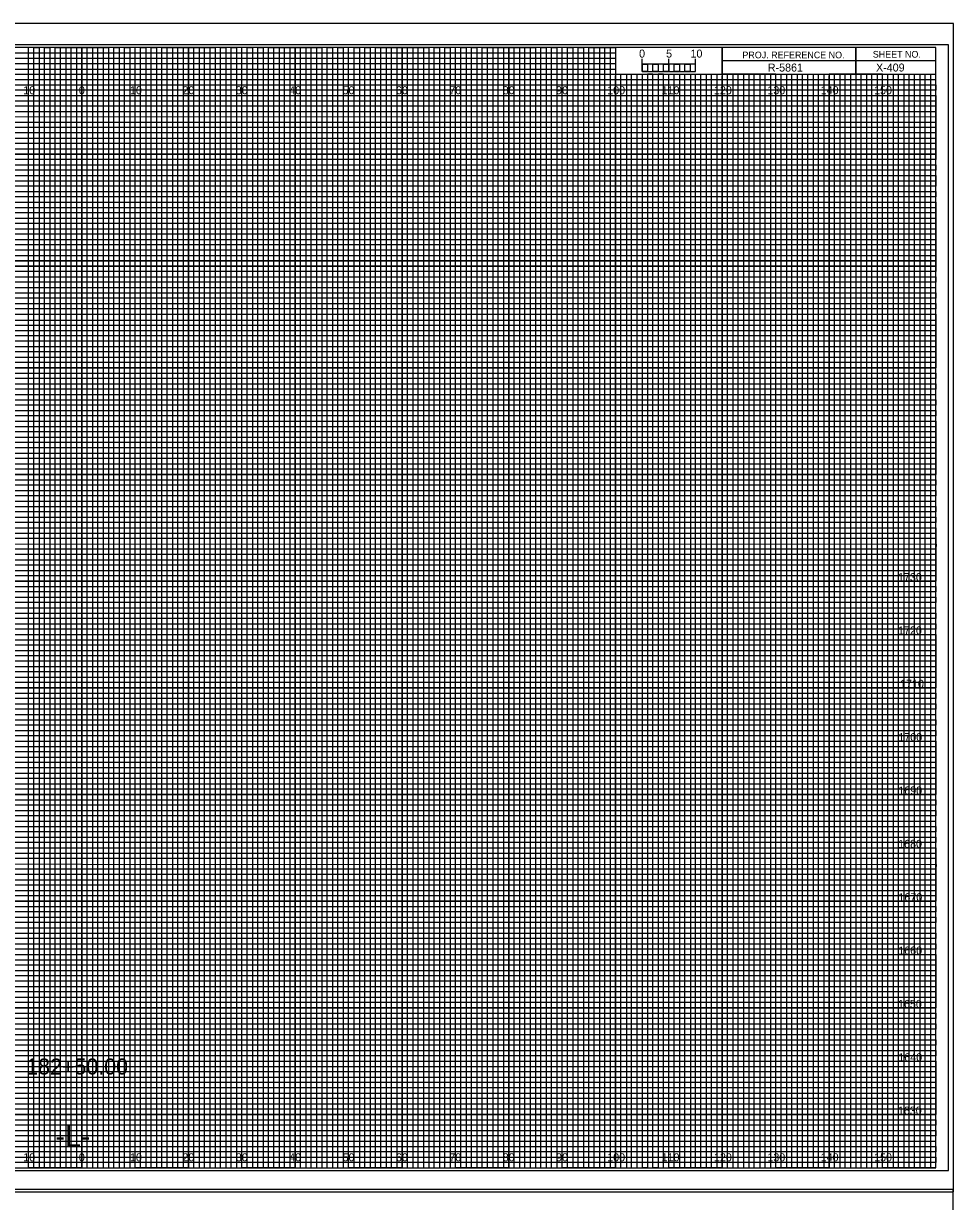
# Model space of a CAD drawing. Extents: x -13 to 323, y -5 to 6154.
# Drawn here: x 149.1 to 323.3, y 1093.7 to 1314.5 of the extents above; entities that cross this region are included whole.
import ezdxf

# ---------------------------------------------------------------- set-up
doc = ezdxf.new("R2010")
doc.units = 0
for name, color, linetype in [('Exist CMT Ground Line', 7, 'Continuous'), ('Prop Horizontal Alignment', 7, 'Continuous'), ('Prop Retaining Wall', 7, 'Continuous'), ('Prop XS Alignment Label', 7, 'Continuous'), ('Prop XS Bar Scale Labels', 7, 'Continuous'), ('Prop XS DDE', 7, 'Continuous'), ('Prop XS DDE Elevations', 7, 'Continuous'), ('Prop XS DDE Slope Text', 7, 'Continuous'), ('Prop XS Earthwork Shape', 7, 'Continuous'), ('Prop XS Elevation Labels', 7, 'Continuous'), ('Prop XS Project Number', 7, 'Continuous'), ('Prop XS Sheet Number', 7, 'Continuous'), ('Prop XS Station Labels', 7, 'Continuous'), ('Raster_Level_0', 7, 'Continuous'), ('Scratch_Level_3', 7, 'Continuous'), ('Sheet Cutting Line CELL', 7, 'Continuous')]:
    doc.layers.add(name, color=color, linetype=linetype)

msp = doc.modelspace()

# ---------------------------------------------------------------- linework, layer by layer
at = {"layer": 'Exist CMT Ground Line'}
for p, q in [((265, 1305.49), (265, 1307.9)), ((265, 1306.9), (265, 1307.9)), ((270, 1305.49), (270, 1307.9)), ((275, 1305.49), (275, 1307.9)), ((275, 1306.9), (275, 1307.9))]:
    msp.add_line(p, q, dxfattribs=at)
for points in [[(275, 1306.9), (265, 1306.9), (265, 1305.49), (275, 1305.49)], [(265, 1306.9), (266, 1306.9), (266, 1305.49), (265, 1305.49)], [(267, 1306.9), (268, 1306.9), (268, 1305.49), (267, 1305.49)], [(269, 1306.9), (270, 1306.9), (270, 1305.49), (269, 1305.49)], [(271, 1306.9), (272, 1306.9), (272, 1305.49), (271, 1305.49)], [(273, 1306.9), (274, 1306.9), (274, 1305.49), (273, 1305.49)]]:
    msp.add_lwpolyline(points, close=True, dxfattribs=at)
at = {"layer": 'Prop Retaining Wall'}
for p, q in [((0, 1309), (260, 1309)), ((260, 1307.98), (0, 1307.98)), ((0, 1307), (260, 1307)), ((260, 1309), (260, 1307.98)), ((260, 1307), (260, 1305.89)), ((260, 1305.89), (0, 1305.89)), ((0, 1304), (320, 1304))]:
    msp.add_line(p, q, dxfattribs=at)
for points in [[(0, 1303), (270, 1303), (320, 1303), (320, 1302), (0, 1302)], [(0, 1301), (320, 1301), (320, 1299), (0, 1299)], [(0, 1298), (320, 1298), (320, 1297), (0, 1296.98)], [(0, 1296), (320, 1296), (320, 1294), (0, 1294)], [(0, 1293), (320, 1293), (320, 1292), (0, 1292)], [(0, 1291), (320, 1291), (320, 1289), (0, 1289)], [(0, 1288), (320, 1288), (320, 1287), (0, 1287)], [(0, 1286), (320, 1286), (320, 1284), (0, 1284)], [(0, 1283), (320, 1283), (320, 1282), (0, 1282)], [(0, 1281), (320, 1281), (320, 1279), (0, 1279)], [(0, 1278), (320, 1278), (320, 1277), (0, 1277)], [(0, 1276), (320, 1276), (320, 1273.95), (320, 1273), (320, 1272), (0, 1272)], [(0, 1274), (320, 1274), (320, 1273), (0, 1273)], [(0, 1271), (320, 1271), (320, 1269), (0, 1269.03)], [(0, 1269.03), (320, 1269), (320, 1268), (0, 1268)], [(0, 1267), (320, 1267), (320, 1266), (0, 1266)], [(0, 1264), (320, 1264), (320, 1263), (0, 1263)], [(0, 1262), (320, 1262), (320, 1261), (0, 1261)], [(-0.07, 1258.89), (320, 1258.89), (320, 1257.88), (-0.07, 1257.88)], [(0, 1257), (320, 1257), (320, 1256), (0, 1256)], [(0, 1254), (320, 1254), (320, 1253), (0, 1253)], [(0, 1252), (320, 1252), (320, 1251), (0, 1251)], [(0, 1249), (320, 1249), (320, 1248), (0, 1248)], [(0, 1247), (320, 1247), (320, 1246), (0, 1246)], [(0, 1244), (320, 1244), (320, 1243), (0, 1243)], [(0, 1242), (320, 1242), (320, 1241), (0, 1241)], [(0, 1239), (320, 1239), (319.99, 1237.98), (0, 1238)], [(0, 1237), (320, 1237), (320, 1236), (0, 1236)], [(0, 1234), (320, 1234), (320, 1233), (0, 1233)], [(0, 1232), (320, 1232), (320, 1231), (0, 1231)], [(0, 1229), (320, 1229), (320, 1228), (0, 1228)], [(0, 1227), (320, 1227), (320, 1226), (0, 1226)], [(0, 1224), (320, 1224), (320, 1223), (0, 1223)], [(0, 1222), (320, 1222), (320, 1221), (0, 1221)], [(0, 1219), (320, 1219), (320, 1218), (0, 1218)], [(0, 1216.99), (320.07, 1216.91), (320, 1216), (0, 1216)], [(0, 1214), (320, 1214), (320, 1213), (0, 1213)], [(0, 1212), (320, 1212), (320, 1211), (0, 1211)], [(0, 1209), (320, 1209), (320, 1208), (0, 1208)], [(0, 1207), (320, 1207), (320, 1206), (0, 1206)], [(0, 1204), (320, 1204), (320, 1203), (0, 1203)], [(0, 1202), (320, 1202), (320, 1201), (0, 1201)], [(0, 1199), (320, 1199), (320, 1198), (0, 1198)], [(0, 1197), (320, 1197), (320, 1196), (0, 1196)], [(0, 1194), (320, 1194), (320, 1193), (0, 1193)], [(0, 1192), (320, 1192), (320, 1191), (0, 1191)], [(0, 1189), (320, 1189), (320, 1188), (0, 1188)], [(0, 1187), (320, 1187), (320, 1186), (0, 1186)], [(0, 1184), (320, 1184), (320, 1183), (0, 1183)], [(0, 1182), (320, 1182), (320, 1181), (0, 1181)], [(0, 1179), (320, 1179), (319.99, 1177.98), (0, 1178)], [(0, 1177), (320, 1177), (320, 1176), (0, 1176)], [(0, 1174), (320, 1174), (320, 1173), (0, 1173)], [(0, 1172), (320, 1172), (320, 1171), (0, 1171)], [(0, 1169), (320, 1169), (320, 1168), (0, 1168)], [(0, 1167), (320, 1167), (320, 1166), (0, 1166)], [(0, 1164), (320, 1164), (320, 1163), (0, 1163)], [(0, 1162), (320, 1162), (320, 1161), (0, 1161)], [(0, 1159), (320, 1159), (320, 1158), (0, 1158)], [(0, 1156.99), (320.07, 1156.91), (320, 1156), (0, 1156)], [(0, 1154), (320, 1154), (320, 1153), (0, 1153)], [(0, 1152), (320, 1152), (320, 1151), (0, 1151)], [(0, 1149), (320, 1149), (320, 1148), (0, 1148)], [(0, 1147), (320, 1147), (320, 1146), (0, 1146)], [(0, 1144), (320, 1144), (320, 1143), (0, 1143)], [(0, 1142), (320, 1142), (320, 1141), (0, 1141)], [(0, 1139), (320, 1139), (320, 1138), (0, 1138)], [(0, 1137), (320, 1137), (320, 1136), (0, 1136)], [(0, 1134), (320, 1134), (320, 1133), (0, 1133)], [(0, 1132), (320, 1132), (320, 1131), (0, 1131)], [(0, 1129), (320, 1129), (320, 1128), (0, 1128)], [(0, 1127), (320, 1127), (320, 1126), (0, 1126)], [(0, 1124), (320, 1124), (320, 1123), (0, 1123)], [(0, 1122), (320, 1122), (320, 1121), (0, 1121)], [(0, 1119), (320, 1119), (320, 1118), (0, 1118)], [(0, 1117), (320, 1117), (320, 1116), (0, 1116)], [(0, 1114), (320, 1114), (320, 1113), (0, 1113)], [(0, 1112), (320, 1112), (320, 1111), (0, 1111)], [(0, 1109), (320, 1109), (320, 1108), (0, 1108)], [(0, 1107), (320, 1107), (320, 1106), (0, 1106)], [(0, 1104), (320, 1104), (320, 1103), (0, 1103)], [(0, 1102), (320, 1102), (320, 1101), (0, 1101)]]:
    msp.add_lwpolyline(points, dxfattribs=at)
at = {"layer": 'Prop XS Alignment Label'}
for p, q in [((305, 1310), (305, 1305)), ((305, 1305), (305, 1310)), ((280, 1307.5), (280, 1305)), ((320, 1307.49), (280, 1307.49)), ((280, 1305), (320, 1305))]:
    msp.add_line(p, q, dxfattribs=at)
for points in [[(320, 1310), (0, 1310), (0, 1100), (320, 1100)], [(280, 1310), (260, 1310), (260, 1305.03), (280, 1305.03)], [(320, 1310), (280, 1310), (280, 1305), (320, 1305)]]:
    msp.add_lwpolyline(points, close=True, dxfattribs=at)
at = {"layer": 'Prop XS DDE'}
for points in [[(-13.4, 1095.5), (323.3, 1095.5), (323.3, 1314.5), (-13.4, 1314.5)], [(-13.44, 876.95), (323.26, 876.95), (323.26, 1095.95), (-13.44, 1095.95)]]:
    msp.add_lwpolyline(points, close=True, dxfattribs=at)
at = {"layer": 'Prop XS DDE Elevations'}
for p, q in [((150, 1100), (150, 1310)), ((160, 1100), (160, 1310)), ((170, 1100), (170, 1310)), ((180, 1100), (180, 1310)), ((190, 1100), (190, 1310)), ((200, 1100), (200, 1310)), ((210, 1100), (210, 1310)), ((220, 1100), (220, 1310)), ((230, 1100), (230, 1310)), ((240, 1100), (240, 1310)), ((250, 1100), (250, 1310)), ((260, 1100), (260, 1304.69)), ((270, 1100), (270, 1304.69)), ((280, 1100), (280, 1304.69)), ((290, 1100), (290, 1304.69)), ((300, 1100), (300, 1304.69)), ((310, 1100), (310, 1304.69)), ((0, 1300), (320, 1300)), ((0, 1290), (320, 1290)), ((0, 1280), (320, 1280)), ((0, 1270), (320, 1270)), ((0, 1260), (320, 1260)), ((0, 1250), (320, 1250)), ((0, 1240), (320, 1240)), ((0, 1230), (320, 1230)), ((0, 1220), (320, 1220)), ((0, 1210), (320, 1210)), ((0, 1200), (320, 1200)), ((0, 1190), (320, 1190)), ((0, 1180), (320, 1180)), ((0, 1170), (320, 1170)), ((0, 1160), (320, 1160)), ((0, 1150), (320, 1150)), ((0, 1140), (320, 1140)), ((0, 1130), (320, 1130)), ((0, 1120), (320, 1120)), ((0, 1110), (320, 1110))]:
    msp.add_line(p, q, dxfattribs=at)
at = {"layer": 'Prop XS DDE Slope Text'}
msp.add_lwpolyline([(-10.8, 1099.5), (322.4, 1099.5), (322.4, 1310.5), (-10.8, 1310.5)], close=True, dxfattribs=at)
at = {"layer": 'Prop XS Earthwork Shape'}
for p, q in [((150, 1310), (140, 1310)), ((150, 1100), (150, 1310)), ((170, 1310), (160, 1310)), ((160, 1310), (160, 1100)), ((170, 1100), (170, 1310)), ((190, 1310), (180, 1310)), ((180, 1310), (180, 1100)), ((190, 1100), (190, 1310)), ((210, 1310), (200, 1310)), ((200, 1310), (200, 1100)), ((210, 1100), (210, 1310)), ((230, 1310), (220, 1310)), ((220, 1310), (220, 1100)), ((230, 1100), (230, 1310)), ((250, 1310), (240, 1310)), ((240, 1310), (240, 1100)), ((250, 1100), (250, 1310)), ((260, 1310), (260, 1100)), ((270, 1100), (270, 1305)), ((290, 1305), (280, 1305)), ((280, 1305), (280, 1100)), ((290, 1100), (290, 1305)), ((310, 1305), (300, 1305)), ((300, 1305), (300, 1100)), ((310, 1100), (310, 1305)), ((160, 1100), (150, 1100)), ((180, 1100), (170, 1100)), ((200, 1100), (190, 1100)), ((220, 1100), (210, 1100)), ((240, 1100), (230, 1100)), ((260, 1100), (250, 1100)), ((280, 1100), (270, 1100)), ((300, 1100), (290, 1100)), ((320, 1100), (310, 1100)), ((320, 1100), (320, 1100))]:
    msp.add_line(p, q, dxfattribs=at)
for points in [[(0, 1300), (320, 1300), (320, 1290), (0, 1290)], [(0, 1280), (320, 1280), (320, 1270), (0, 1270)], [(0, 1260), (320, 1260), (320, 1250), (0, 1250)], [(0, 1240), (320, 1240), (320, 1230), (0, 1230)], [(0, 1220), (320, 1220), (320, 1210), (0, 1210)], [(0, 1200), (320, 1200), (320, 1190), (0, 1190)], [(0, 1180), (320, 1180), (320, 1170), (0, 1170)], [(0, 1160), (320, 1160), (320, 1150), (0, 1150)], [(0, 1140), (320, 1140), (320, 1130), (0, 1130)], [(0, 1120), (320, 1120), (320, 1110), (0, 1110)]]:
    msp.add_lwpolyline(points, dxfattribs=at)
at = {"layer": 'Prop XS Elevation Labels'}
for p, q in [((267, 1305), (266.01, 1305)), ((266.01, 1305), (266.01, 1100)), ((267, 1100), (267, 1305)), ((269, 1305), (268, 1305)), ((268, 1305), (268, 1100)), ((269, 1100), (269, 1305)), ((266.01, 1100), (265, 1100)), ((268, 1100), (267, 1100))]:
    msp.add_line(p, q, dxfattribs=at)
for points in [[(150, 1100), (151, 1100), (151, 1310), (152, 1310), (152, 1100)], [(152, 1100), (153, 1100), (153, 1310), (154, 1310), (154, 1100)], [(155, 1100), (156, 1100), (156, 1310), (157, 1310), (157, 1100)], [(157, 1100), (158, 1100), (158, 1310), (159, 1310), (159, 1100)], [(160, 1100), (161, 1100), (161, 1310), (162, 1310), (162, 1100)], [(162, 1100), (163, 1100), (163, 1310), (164, 1310), (164, 1100)], [(165, 1100), (166, 1100), (166, 1310), (167, 1310), (167, 1100)], [(167, 1100), (168, 1100), (168, 1310), (169, 1310), (169, 1100)], [(170, 1100), (171, 1100), (171, 1310), (172, 1310), (172, 1100)], [(172, 1100), (173, 1100), (173, 1310), (174, 1310), (174, 1100)], [(175, 1100), (176, 1100), (176, 1310), (177, 1310), (177, 1100)], [(177, 1100), (178, 1100), (178, 1310), (179, 1310), (179, 1100)], [(180, 1100), (181, 1100), (181, 1310), (182, 1310), (182, 1100)], [(182, 1100), (183, 1100), (183, 1310), (184, 1310), (184, 1100)], [(185, 1100), (186, 1100), (186, 1310), (187, 1310), (187, 1100)], [(187, 1100), (188, 1100), (188, 1310), (189, 1310), (189, 1100)], [(190, 1100), (191, 1100), (191, 1310), (192, 1310), (192, 1100)], [(192, 1100), (193, 1100), (193, 1310), (194, 1310), (194, 1100)], [(195, 1100), (196, 1100), (196, 1310), (197, 1310), (197, 1100)], [(197, 1100), (198, 1100), (198, 1310), (199, 1310), (199, 1100)], [(200, 1100), (201, 1100), (201, 1310), (202, 1310), (202, 1100)], [(202, 1100), (203, 1100), (203, 1310), (204, 1310), (204, 1100)], [(205, 1100), (206, 1100), (206, 1310), (207, 1310), (207, 1100)], [(207, 1100), (208, 1100), (208, 1310), (209, 1310), (209, 1100)], [(210, 1100), (211, 1100), (211, 1310), (212, 1310), (212, 1100)], [(212, 1100), (213, 1100), (213, 1310), (214, 1310), (214, 1100)], [(215, 1100), (216, 1100), (216, 1310), (217, 1310), (217, 1100)], [(217, 1100), (218, 1100), (218, 1310), (219, 1310), (219, 1100)], [(220, 1100), (221, 1100), (221, 1310), (222, 1310), (222, 1100)], [(222, 1100), (223, 1100), (223, 1310), (224, 1310), (224, 1100)], [(225, 1100), (226, 1100), (226, 1310), (227, 1310), (227, 1100)], [(227, 1100), (228, 1100), (228, 1310), (229, 1310), (229, 1100)], [(230, 1100), (231, 1100), (231, 1310), (232, 1310), (232, 1100)], [(232, 1100), (233, 1100), (233, 1310), (234, 1310), (234, 1100)], [(235, 1100), (236, 1100), (236, 1310), (237, 1310), (237, 1100)], [(237, 1100), (238, 1100), (238, 1310), (239, 1310), (239, 1100)], [(240, 1100), (241, 1100), (241, 1310), (242, 1310), (242, 1100)], [(242, 1100), (243, 1100), (243, 1310), (244, 1310), (244, 1100)], [(245, 1100), (246, 1100), (246, 1310), (247, 1310), (247, 1100)], [(247, 1100), (248, 1100), (248, 1310), (249, 1310), (249, 1100)], [(250, 1100), (251, 1100), (251, 1310), (252, 1310), (252, 1100)], [(252, 1100), (253, 1100), (253, 1310), (254, 1310), (254, 1100)], [(255, 1100), (256, 1100), (256, 1310), (257, 1310), (257, 1100)], [(257, 1100), (258, 1100), (258, 1310), (259, 1310), (259, 1100)], [(260, 1100), (261, 1100), (261, 1305), (262.02, 1305), (262.02, 1100)], [(262, 1100), (263, 1100), (263, 1305), (263.99, 1305), (263.99, 1100)], [(270, 1100), (270.98, 1100), (270.98, 1305), (272, 1305), (272, 1100)], [(272, 1100), (273, 1100), (273, 1305), (274.05, 1305), (274.05, 1100)], [(275, 1100), (276, 1100), (276, 1305), (277, 1305), (277, 1100)], [(277, 1100), (278, 1100), (278, 1305), (279, 1305), (279, 1100)], [(280, 1100), (281, 1100), (281, 1305), (282, 1305), (282, 1100)], [(282, 1100), (283, 1100), (283, 1305), (284, 1305), (284, 1100)], [(285, 1100), (286, 1100), (286, 1305), (287, 1305), (287, 1100)], [(287, 1100), (288, 1100), (288, 1305), (289, 1305), (289, 1100)], [(290, 1100), (291, 1100), (291, 1305), (292, 1305), (292, 1100)], [(292, 1100), (293, 1100), (293, 1305), (294, 1305), (294, 1100)], [(295, 1100), (296, 1100), (296, 1305), (297, 1305), (297, 1100)], [(297, 1100), (298, 1100), (298, 1305), (299, 1305), (299, 1100)], [(300, 1100), (301, 1100), (301, 1305), (302, 1305), (302, 1100)], [(302, 1100), (303, 1100), (303, 1305), (304, 1305), (304, 1100)], [(305, 1100), (306, 1100), (306, 1305), (307, 1305), (307, 1100)], [(307, 1100), (308, 1100), (308, 1305), (309, 1305), (309, 1100)], [(310, 1100), (311, 1100), (311, 1305), (312, 1305), (312, 1100)], [(312, 1100), (313, 1100), (313, 1305), (314, 1305), (314, 1100)], [(315, 1100), (316, 1100), (316, 1305), (317, 1305), (317, 1100)], [(317, 1100), (318, 1100), (318, 1305), (319, 1305), (319, 1100)]]:
    msp.add_lwpolyline(points, dxfattribs=at)
at = {"layer": 'Prop XS Station Labels'}
for points in [[(145, 1100), (155, 1100), (155, 1310), (165, 1310), (165, 1100), (175, 1100), (175, 1310), (185, 1310), (185, 1100), (195, 1100), (195, 1310), (205, 1310), (205, 1100), (215, 1100), (215, 1310), (225, 1310), (225, 1100), (235, 1100), (235, 1310), (245, 1310), (245, 1100), (255, 1100), (255, 1310), (259.93, 1310), (260, 1310), (260, 1305), (264.99, 1305), (264.99, 1100), (275, 1100), (275, 1305), (285, 1305), (285, 1100), (295, 1100), (295, 1305), (305, 1305), (305, 1100), (315, 1100), (315, 1305)], [(0, 1305), (275, 1305)], [(0, 1285), (320, 1285), (320, 1295), (0, 1295)], [(0, 1265), (320, 1265), (320, 1275), (0, 1275)], [(0, 1245), (320, 1245), (320, 1255), (0, 1255)], [(0, 1225), (320, 1225), (320, 1235), (0, 1235)], [(0, 1205), (320, 1205), (320, 1215), (0, 1215)], [(0, 1185), (320, 1185), (320, 1195), (0, 1195)], [(0, 1165), (320, 1165), (320, 1175), (0, 1175)], [(0, 1145), (320, 1145), (320, 1155), (0, 1155)], [(0, 1125), (320, 1125), (320, 1135), (0, 1135)], [(0, 1105), (320, 1105), (320, 1115), (0, 1115)]]:
    msp.add_lwpolyline(points, dxfattribs=at)
at = {"layer": 'Sheet Cutting Line CELL'}
for p, q in [((323.3, 1314.5), (-13.4, 1314.5)), ((323.26, 1095.95), (-13.44, 1095.95)), ((-13.4, 1095.5), (323.3, 1095.5))]:
    msp.add_line(p, q, dxfattribs=at)

# ---------------------------------------------------------------- texts
at = {"layer": 'Exist CMT Ground Line'}
msp.add_text('0', height=1.5, dxfattribs=at).set_placement((264.41, 1308.12))
at = {"layer": 'Prop Horizontal Alignment'}
msp.add_text('182+50.00', height=3, dxfattribs=at).set_placement((149.59, 1117.52))
at = {"layer": 'Prop XS Alignment Label'}
for s, height, p in [('PROJ. REFERENCE NO.', 1.25, (283.77, 1307.99)), ('SHEET NO.', 1.25, (308.19, 1308.12)), ('-L-', 4, (155.06, 1104))]:
    msp.add_text(s, height=height, dxfattribs=at).set_placement(p)
at = {"layer": 'Prop XS Bar Scale Labels'}
for s, p in [('5', (269.47, 1308.12)), ('10', (274.04, 1308.12))]:
    msp.add_text(s, height=1.5, dxfattribs=at).set_placement(p)
at = {"layer": 'Prop XS Project Number'}
msp.add_text('R-5861', height=1.5, dxfattribs=at).set_placement((288.53, 1305.5))
at = {"layer": 'Prop XS Sheet Number'}
msp.add_text('X-409', height=1.5, dxfattribs=at).set_placement((308.8, 1305.51))
at = {"layer": 'Raster_Level_0'}
for s, p in [('10', (149.04, 1301.25)), ('0', (159.45, 1301.25)), ('0', (159.45, 1301.25)), ('10', (169.04, 1301.25)), ('20', (178.86, 1301.25)), ('30', (188.86, 1301.25)), ('40', (198.86, 1301.25)), ('50', (208.86, 1301.25)), ('60', (218.86, 1301.25)), ('70', (228.86, 1301.25)), ('80', (238.86, 1301.25)), ('90', (248.86, 1301.25)), ('100', (258.44, 1301.25)), ('110', (268.62, 1301.25)), ('120', (278.44, 1301.25)), ('130', (288.44, 1301.25)), ('140', (298.44, 1301.25)), ('150', (308.44, 1301.25)), ('10', (149.04, 1101.25)), ('0', (159.45, 1101.25)), ('0', (159.45, 1101.25)), ('10', (169.04, 1101.25)), ('20', (178.86, 1101.25)), ('30', (188.86, 1101.25)), ('40', (198.86, 1101.25)), ('50', (208.86, 1101.25)), ('60', (218.86, 1101.25)), ('70', (228.86, 1101.25)), ('80', (238.86, 1101.25)), ('90', (248.86, 1101.25)), ('100', (258.44, 1101.25)), ('110', (268.62, 1101.25)), ('120', (278.44, 1101.25)), ('130', (288.44, 1101.25)), ('140', (298.44, 1101.25)), ('150', (308.44, 1101.25))]:
    msp.add_text(s, height=1.5, dxfattribs=at).set_placement(p)
at = {"layer": 'Scratch_Level_3'}
for s, p in [('1730', (312.92, 1210)), ('1720', (312.93, 1200)), ('1710', (313.31, 1190)), ('1700', (312.98, 1180)), ('1690', (312.97, 1170)), ('1680', (312.95, 1160)), ('1670', (313, 1150)), ('1660', (312.97, 1140)), ('1650', (312.92, 1130)), ('1640', (312.97, 1120)), ('1630', (312.89, 1110))]:
    msp.add_text(s, height=1.5, dxfattribs=at).set_placement(p)

doc.saveas('drawing.dxf')
